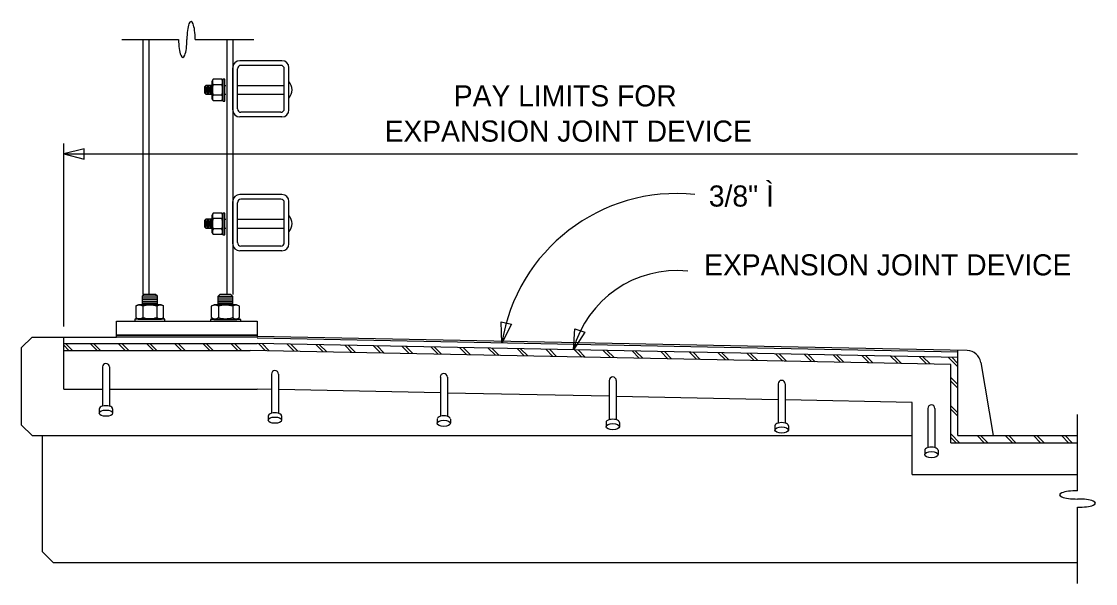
# Model space of a CAD drawing. Extents: x 19590 to 20151, y 19944 to 20103.
# Drawn here: x 19849.63 to 19873.36, y 20050.52 to 20062.93 of the extents above; entities that cross this region are included whole.
import ezdxf

# ---------------------------------------------------------------- set-up
doc = ezdxf.new("R2010")
doc.units = 0
for name, color, linetype in [('DETAIL_PR', 7, 'Continuous'), ('Level 1', 7, 'Continuous'), ('MT_PAVT_MRKGS_EX', 7, 'Continuous'), ('MT_PAVT_MRKGS_EX_REF', 7, 'Continuous'), ('PAVT_MRKGS_QUANT', 7, 'Continuous')]:
    doc.layers.add(name, color=color, linetype=linetype)

# ---------------------------------------------------------------- blocks, each defined once
blk = doc.blocks.new('BRE')
at = {"layer": 'DETAIL_PR'}
for centre, ratio, start_param, end_param in [((0, 0.098), 0.230206, 4.712389, 7.853982), ((0, -0.098), 0.230204, 1.570796, 4.712389)]:
    blk.add_ellipse(centre, major_axis=(-0.427, 0), ratio=ratio, start_param=start_param, end_param=end_param, dxfattribs=at)
blk = doc.blocks.new('EJ3H')
at = {"layer": 'MT_PAVT_MRKGS_EX'}
for p, q in [((40.225, -33.577), (41.479, -33.577)), ((40.691, -33.577), (40.691, -39.206)), ((40.82, -33.577), (40.82, -39.206)), ((41.846, -33.577), (43.141, -33.577)), ((42.546, -33.577), (42.546, -39.209)), ((42.674, -33.577), (42.674, -39.209)), ((43.762, -34.044), (42.83, -34.044)), ((43.736, -34.148), (42.855, -34.148)), ((42.674, -35.132), (42.674, -34.199)), ((42.777, -35.106), (42.777, -34.226)), ((43.813, -35.106), (43.813, -34.226)), ((43.917, -35.132), (43.917, -34.199)), ((42.077, -34.589), (42.077, -34.785)), ((42.104, -34.628), (42.104, -34.748)), ((42.118, -34.589), (42.118, -34.785)), ((42.132, -34.628), (42.132, -34.748)), ((42.145, -34.589), (42.145, -34.785)), ((42.166, -34.628), (42.166, -34.748)), ((42.185, -34.589), (42.185, -34.785)), ((42.199, -34.628), (42.199, -34.748)), ((42.43, -34.575), (42.24, -34.575)), ((42.498, -34.589), (42.525, -34.589)), ((42.777, -34.59), (43.813, -34.59)), ((42.43, -34.802), (42.24, -34.802)), ((42.498, -34.786), (42.525, -34.786)), ((42.777, -34.786), (43.813, -34.786)), ((43.762, -35.287), (42.83, -35.287)), ((43.736, -35.183), (42.855, -35.183)), ((43.762, -36.998), (42.83, -36.998)), ((42.674, -38.087), (42.674, -37.154)), ((42.777, -38.06), (42.777, -37.18)), ((43.736, -37.102), (42.855, -37.102)), ((43.813, -38.06), (43.813, -37.18)), ((43.917, -38.087), (43.917, -37.154)), ((42.077, -37.544), (42.077, -37.74)), ((42.104, -37.583), (42.104, -37.703)), ((42.118, -37.544), (42.118, -37.74)), ((42.132, -37.583), (42.132, -37.703)), ((42.145, -37.544), (42.145, -37.74)), ((42.166, -37.583), (42.166, -37.703)), ((42.185, -37.544), (42.185, -37.74)), ((42.199, -37.583), (42.199, -37.703)), ((42.43, -37.529), (42.24, -37.529)), ((42.498, -37.544), (42.525, -37.544)), ((42.777, -37.545), (43.813, -37.545)), ((42.43, -37.756), (42.24, -37.756)), ((42.498, -37.741), (42.525, -37.741)), ((42.777, -37.741), (43.813, -37.741)), ((43.736, -38.138), (42.855, -38.138)), ((43.762, -38.242), (42.83, -38.242)), ((41.011, -39.246), (40.672, -39.246)), ((41.011, -39.286), (40.672, -39.286)), ((41.011, -39.327), (40.672, -39.327)), ((41.011, -39.367), (40.672, -39.367)), ((42.673, -39.249), (42.347, -39.249)), ((42.673, -39.288), (42.347, -39.288)), ((42.673, -39.329), (42.347, -39.329)), ((42.673, -39.369), (42.347, -39.369)), ((41.011, -39.407), (40.672, -39.407)), ((40.685, -39.461), (40.685, -39.715)), ((40.998, -39.461), (40.998, -39.715)), ((42.673, -39.409), (42.347, -39.409)), ((42.361, -39.463), (42.361, -39.717)), ((42.673, -39.463), (42.673, -39.717)), ((38.241, -40.147), (38.008, -40.38)), ((38.241, -40.147), (40.107, -40.147)), ((38.941, -41.3), (38.941, -40.147)), ((38.941, -40.289), (43.217, -40.289)), ((39.057, -40.444), (38.941, -40.328)), ((39.135, -40.444), (38.98, -40.289)), ((39.679, -40.444), (39.524, -40.289)), ((39.757, -40.444), (39.602, -40.289)), ((40.301, -40.444), (40.146, -40.289)), ((40.379, -40.444), (40.224, -40.289)), ((40.923, -40.444), (40.768, -40.289)), ((41.001, -40.444), (40.846, -40.289)), ((41.545, -40.444), (41.39, -40.289)), ((41.623, -40.444), (41.468, -40.289)), ((42.168, -40.444), (42.012, -40.289)), ((42.245, -40.444), (42.09, -40.289)), ((42.79, -40.444), (42.634, -40.289)), ((42.867, -40.444), (42.712, -40.289)), ((58.898, -40.447), (43.217, -40.133)), ((58.69, -40.482), (43.217, -40.172)), ((58.69, -40.598), (43.217, -40.289)), ((43.401, -40.448), (43.243, -40.289)), ((43.481, -40.449), (43.322, -40.291)), ((44.034, -40.458), (43.878, -40.303)), ((44.115, -40.462), (43.957, -40.303)), ((44.671, -40.473), (44.512, -40.315)), ((44.75, -40.475), (44.591, -40.316)), ((45.305, -40.486), (45.147, -40.327)), ((45.385, -40.488), (45.226, -40.329)), ((38.008, -42.091), (38.008, -40.38)), ((38.941, -40.444), (43.062, -40.444)), ((58.534, -40.751), (43.062, -40.441)), ((45.94, -40.499), (45.781, -40.34)), ((46.019, -40.5), (45.861, -40.342)), ((46.575, -40.511), (46.416, -40.353)), ((46.654, -40.513), (46.495, -40.354)), ((47.21, -40.524), (47.051, -40.365)), ((47.289, -40.526), (47.13, -40.367)), ((47.844, -40.537), (47.686, -40.378)), ((47.924, -40.538), (47.765, -40.38)), ((48.479, -40.549), (48.32, -40.391)), ((48.558, -40.551), (48.4, -40.392)), ((49.114, -40.562), (48.955, -40.403)), ((49.193, -40.564), (49.034, -40.405)), ((49.748, -40.575), (49.59, -40.416)), ((49.828, -40.576), (49.669, -40.418)), ((50.383, -40.588), (50.224, -40.429)), ((50.462, -40.589), (50.304, -40.43)), ((51.018, -40.6), (50.859, -40.442)), ((51.097, -40.602), (50.939, -40.443)), ((51.653, -40.613), (51.494, -40.454)), ((51.732, -40.615), (51.573, -40.456)), ((52.287, -40.626), (52.129, -40.467)), ((52.367, -40.627), (52.208, -40.469)), ((52.922, -40.638), (52.763, -40.48)), ((53.001, -40.64), (52.843, -40.481)), ((53.557, -40.651), (53.398, -40.492)), ((53.636, -40.653), (53.477, -40.494)), ((54.191, -40.664), (54.033, -40.505)), ((54.271, -40.665), (54.112, -40.507)), ((54.826, -40.676), (54.667, -40.518)), ((54.906, -40.678), (54.747, -40.519)), ((55.461, -40.689), (55.302, -40.53)), ((55.54, -40.691), (55.382, -40.532)), ((56.096, -40.702), (55.937, -40.543)), ((56.175, -40.703), (56.016, -40.545)), ((56.73, -40.714), (56.572, -40.556)), ((56.81, -40.716), (56.651, -40.557)), ((57.365, -40.727), (57.206, -40.568)), ((58.69, -42.324), (58.69, -40.443)), ((57.446, -40.73), (57.286, -40.57)), ((58, -40.74), (57.841, -40.581)), ((58.079, -40.741), (57.92, -40.583)), ((58.69, -40.808), (58.476, -40.594)), ((58.534, -42.48), (58.534, -40.751)), ((58.69, -40.73), (58.555, -40.595)), ((59.199, -40.707), (59.468, -42.324)), ((39.796, -40.808), (39.796, -41.673)), ((39.952, -40.808), (39.952, -41.673)), ((43.528, -40.964), (43.528, -41.828)), ((43.684, -40.964), (43.684, -41.828)), ((47.26, -41.032), (47.26, -41.897)), ((47.415, -41.032), (47.415, -41.897)), ((58.69, -41.197), (58.534, -41.041)), ((50.991, -41.107), (50.991, -41.971)), ((51.146, -41.107), (51.146, -41.971)), ((54.722, -41.181), (54.722, -42.046)), ((54.878, -41.181), (54.878, -42.046)), ((58.69, -41.275), (58.534, -41.119)), ((38.941, -41.3), (39.796, -41.3)), ((39.952, -41.3), (41.662, -41.3)), ((41.662, -41.3), (43.217, -41.3)), ((43.528, -41.306), (43.217, -41.3)), ((47.26, -41.381), (43.684, -41.309)), ((50.991, -41.455), (47.415, -41.384)), ((54.722, -41.53), (51.146, -41.458)), ((39.726, -41.733), (39.726, -41.828)), ((40.021, -41.733), (40.021, -41.828)), ((57.679, -41.589), (54.878, -41.533)), ((57.679, -43.18), (57.679, -41.589)), ((58.029, -41.723), (58.029, -42.589)), ((58.185, -41.723), (58.185, -42.589)), ((58.69, -41.819), (58.534, -41.663)), ((58.69, -41.897), (58.534, -41.741)), ((43.458, -41.888), (43.458, -41.984)), ((43.754, -41.888), (43.754, -41.984)), ((47.19, -41.957), (47.19, -42.052)), ((47.485, -41.957), (47.485, -42.052)), ((61.334, -43.54), (61.334, -41.858)), ((38.241, -42.324), (38.008, -42.091)), ((50.921, -42.031), (50.921, -42.127)), ((51.216, -42.031), (51.216, -42.127)), ((54.652, -42.106), (54.652, -42.201)), ((54.948, -42.106), (54.948, -42.201)), ((38.241, -42.324), (57.679, -42.324)), ((38.474, -44.89), (38.474, -42.324)), ((58.729, -42.48), (58.534, -42.285)), ((58.651, -42.48), (58.534, -42.363)), ((58.69, -42.324), (61.334, -42.324)), ((59.273, -42.48), (59.118, -42.324)), ((59.351, -42.48), (59.195, -42.324)), ((59.895, -42.48), (59.74, -42.324)), ((59.973, -42.48), (59.817, -42.324)), ((60.517, -42.48), (60.362, -42.324)), ((60.595, -42.48), (60.439, -42.324)), ((61.139, -42.48), (60.984, -42.324)), ((61.217, -42.48), (61.061, -42.324)), ((57.959, -42.648), (57.959, -42.743)), ((58.255, -42.648), (58.255, -42.743)), ((58.534, -42.48), (61.334, -42.48)), ((57.679, -43.18), (61.334, -43.18)), ((61.334, -45.59), (61.334, -43.907)), ((38.474, -44.89), (38.707, -45.123)), ((38.707, -45.123), (61.334, -45.123))]:
    blk.add_line(p, q, dxfattribs=at)
for points in [[(42.213, -34.589), (42.077, -34.589), (42.05, -34.621), (42.05, -34.755), (42.077, -34.785), (42.213, -34.785)], [(42.24, -34.453), (42.213, -34.507), (42.213, -34.883), (42.24, -34.922), (42.43, -34.922), (42.457, -34.883), (42.457, -34.507), (42.43, -34.453), (42.24, -34.453)], [(42.457, -34.453), (42.457, -34.936), (42.498, -34.936), (42.498, -34.453), (42.457, -34.453)], [(42.24, -37.408), (42.213, -37.462), (42.213, -37.837), (42.24, -37.877), (42.43, -37.877), (42.457, -37.837), (42.457, -37.462), (42.43, -37.408), (42.24, -37.408)], [(42.457, -37.408), (42.457, -37.891), (42.498, -37.891), (42.498, -37.408), (42.457, -37.408)], [(42.213, -37.544), (42.077, -37.544), (42.05, -37.575), (42.05, -37.71), (42.077, -37.74), (42.213, -37.74)], [(41.011, -39.434), (41.011, -39.246), (40.971, -39.206), (40.712, -39.206), (40.672, -39.246), (40.672, -39.434)], [(42.673, -39.436), (42.673, -39.249), (42.632, -39.209), (42.388, -39.209), (42.347, -39.249), (42.347, -39.436)], [(40.591, -39.755), (41.093, -39.755), (41.147, -39.715), (41.147, -39.461), (41.093, -39.434), (40.591, -39.434), (40.536, -39.461), (40.536, -39.715), (40.591, -39.755)], [(42.266, -39.758), (42.755, -39.758), (42.823, -39.717), (42.823, -39.463), (42.755, -39.436), (42.266, -39.436), (42.198, -39.463), (42.198, -39.717), (42.266, -39.758)], [(41.174, -39.755), (40.509, -39.755), (40.509, -39.795), (41.174, -39.795), (41.174, -39.755)], [(42.85, -39.758), (42.185, -39.758), (42.185, -39.797), (42.85, -39.797), (42.85, -39.758)]]:
    blk.add_lwpolyline(points, dxfattribs=at)
for points in [[(43.217, -40.108), (40.107, -40.108), (40.107, -39.797), (43.217, -39.797)], [(40.107, -40.108), (43.217, -40.108), (43.217, -40.147), (40.107, -40.147)]]:
    blk.add_lwpolyline(points, close=True, dxfattribs=at)
for centre, radius, start, end in [((42.829, -34.199), 0.155, 90, 180), ((42.855, -34.225), 0.0777, 90, 180), ((43.736, -34.225), 0.0777, 0, 90), ((43.762, -34.199), 0.155, 0, 90), ((43.707, -34.688), 0.277, 319.1029, 40.8971), ((42.855, -35.106), 0.0777, 180, 270), ((43.736, -35.106), 0.0777, 270, 360), ((42.829, -35.131), 0.155, 180, 270), ((43.762, -35.131), 0.155, 270, 360), ((42.829, -37.154), 0.155, 90, 180), ((43.762, -37.154), 0.155, 0, 90), ((42.855, -37.18), 0.0777, 90, 180), ((43.736, -37.18), 0.0777, 0, 90), ((43.707, -37.643), 0.277, 319.1029, 40.8971), ((42.829, -38.086), 0.155, 180, 270), ((42.855, -38.06), 0.0777, 180, 270), ((43.736, -38.06), 0.0777, 270, 360), ((43.762, -38.086), 0.155, 270, 360), ((58.892, -40.758), 0.311, 9.4315, 88.8542), ((39.874, -40.808), 0.0778, 0, 180), ((43.606, -40.964), 0.0778, 0, 180), ((47.337, -41.032), 0.0778, 0, 180), ((51.069, -41.107), 0.0778, 0, 180), ((54.8, -41.181), 0.0778, 0, 180), ((58.107, -41.723), 0.0778, 0, 180)]:
    blk.add_arc(centre, radius, start, end, dxfattribs=at)
for centre, major_axis, ratio, start_param, end_param in [((42.331, -34.513), (0.106, 0), 0.985841, 2.541474, 3.741711), ((42.621, -34.689), (0.395, 0), 0.985841, 2.834625, 3.44856), ((42.344, -34.513), (0.106, 0), 0.985841, 5.683067, 6.883304), ((42.055, -34.689), (0.395, 0), 0.985841, 5.976218, 6.590153), ((42.331, -34.866), (0.106, 0), 0.985841, 2.541474, 3.741711), ((42.344, -34.866), (0.106, 0), 0.985841, 5.683067, 6.883304), ((42.331, -37.467), (0.106, 0), 0.985841, 2.541474, 3.741711), ((42.344, -37.467), (0.106, 0), 0.985841, 5.683067, 6.883304), ((42.621, -37.644), (0.395, 0), 0.985841, 2.834625, 3.44856), ((42.055, -37.644), (0.395, 0), 0.985841, 5.976218, 6.590153), ((42.331, -37.821), (0.106, 0), 0.985841, 2.541474, 3.741711), ((42.344, -37.821), (0.106, 0), 0.985841, 5.683067, 6.883304), ((40.61, -39.578), (0.138, 0), 0.985841, 0.970676, 2.170917), ((40.843, -39.949), (0.514, 0), 0.985841, 1.263828, 1.877765), ((41.076, -39.578), (0.138, 0), 0.985841, 0.970677, 2.170916), ((42.28, -39.58), (0.138, 0), 0.985841, 0.970676, 2.170917), ((42.513, -39.951), (0.514, 0), 0.985841, 1.263828, 1.877765), ((42.746, -39.58), (0.138, 0), 0.985841, 0.970677, 2.170916), ((40.61, -39.604), (0.138, 0), 0.985841, 4.112273, 5.312505), ((40.843, -39.233), (0.514, 0), 0.985841, 4.405422, 5.019356), ((41.076, -39.604), (0.138, 0), 0.985841, 4.112272, 5.312505), ((42.28, -39.606), (0.138, 0), 0.985841, 4.112273, 5.312505), ((42.513, -39.235), (0.514, 0), 0.985841, 4.405422, 5.019356), ((42.746, -39.606), (0.138, 0), 0.985841, 4.112272, 5.312505), ((39.874, -41.732), (0.148, 0), 0.466726, 0, 3.141593), ((43.606, -41.888), (0.148, 0), 0.466726, 0, 3.141593), ((47.337, -41.956), (0.148, 0), 0.466726, 0, 3.141593), ((51.069, -42.031), (0.148, 0), 0.466726, 0, 3.141593), ((54.8, -42.106), (0.148, 0), 0.466726, 0, 3.141593), ((58.107, -42.648), (0.148, 0), 0.466726, 0, 3.141593)]:
    blk.add_ellipse(centre, major_axis=major_axis, ratio=ratio, start_param=start_param, end_param=end_param, dxfattribs=at)
for centre in [(39.874, -41.828), (43.606, -41.983), (47.337, -42.052), (51.069, -42.127), (54.8, -42.201), (58.107, -42.743)]:
    blk.add_ellipse(centre, major_axis=(0.148, 0), ratio=0.466726, dxfattribs=at)
at = {"layer": 'MT_PAVT_MRKGS_EX_REF'}
for p, q in [((38.941, -39.914), (38.941, -35.871)), ((38.941, -36.104), (61.334, -36.104))]:
    blk.add_line(p, q, dxfattribs=at)
for centre, radius, end in [((52.483, -40.89), 3.912, 171.0299), ((52.483, -41.046), 2.367, 164.8834)]:
    blk.add_arc(centre, radius, 84.1624, end, dxfattribs=at)
at = {"layer": 'PAVT_MRKGS_QUANT'}
for p, q in [((39.392, -35.987), (38.941, -36.104)), ((39.392, -36.221), (39.392, -35.987)), ((38.941, -36.104), (39.392, -36.221)), ((48.619, -40.28), (48.604, -39.814)), ((48.604, -39.814), (48.831, -39.865)), ((48.831, -39.865), (48.619, -40.28)), ((50.198, -40.428), (50.233, -39.963)), ((50.454, -40.038), (50.198, -40.428)), ((50.233, -39.963), (50.454, -40.038))]:
    blk.add_line(p, q, dxfattribs=at)
at = {"layer": 'PAVT_MRKGS_QUANT', "xscale": 0.9330357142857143, "yscale": 0.9330357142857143}
for p, rotation in [((41.662, -33.577), 90), ((61.334, -43.724), 180)]:
    blk.add_blockref('BRE', p, dxfattribs=dict(at, rotation=rotation))
at = {"layer": 'MT_PAVT_MRKGS_EX_REF'}
for s, height, p in [('PAY LIMITS FOR', 0.46652, (47.558, -35.054)), ('EXPANSION JOINT DEVICE', 0.46652, (46.028, -35.832)), ('3/8" Ì', 0.4665, (53.191, -37.266)), ('EXPANSION JOINT DEVICE', 0.46652, (53.087, -38.786))]:
    blk.add_text(s, height=height, dxfattribs=at).set_placement(p)

msp = doc.modelspace()

# ---------------------------------------------------------------- block references
at = {"layer": 'Level 1'}
msp.add_blockref('EJ3H', (19811.624, 20096.106), dxfattribs=at)

doc.saveas('drawing.dxf')
